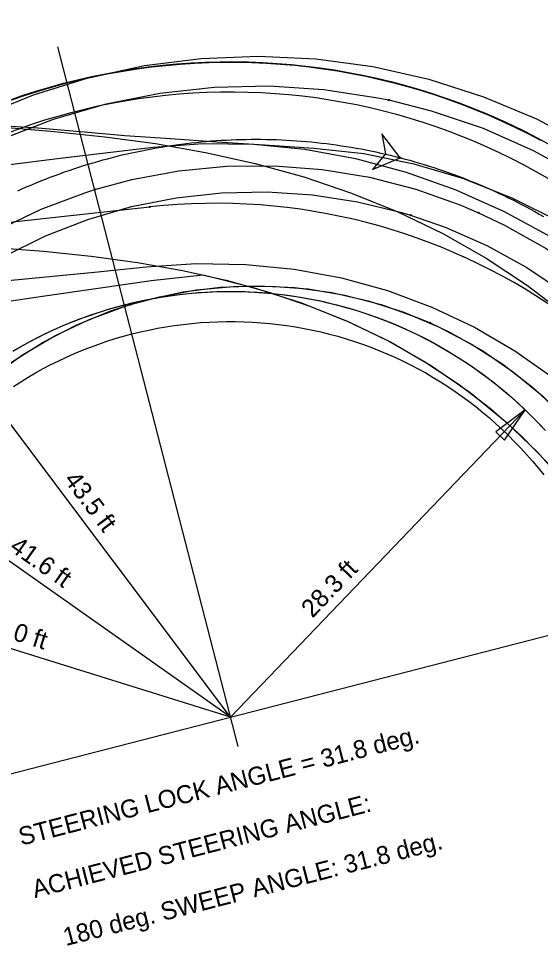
# Model space of a CAD drawing. Extents: x 916040 to 917457, y 328936 to 330267.
# Drawn here: x 916684.3 to 916719, y 329778.6 to 329840.2 of the extents above; entities that cross this region are included whole.
import ezdxf

# ---------------------------------------------------------------- set-up
doc = ezdxf.new("R2010")
doc.units = 0
for name, color, linetype in [('EB_LeftontoManchester_WB67', 7, 'Continuous'), ('EB_LeftontoManchester_WB67_v2', 7, 'Continuous'), ('SU_IntoDriveway', 7, 'Continuous'), ('SU_IntoDriveway_Lt', 7, 'Continuous'), ('SU_IntoDriveway_Rt', 7, 'Continuous')]:
    doc.layers.add(name, color=color, linetype=linetype)

msp = doc.modelspace()

# ---------------------------------------------------------------- linework, layer by layer
at = {"layer": 'EB_LeftontoManchester_WB67'}
msp.add_arc((916768.512, 329810.214), 100, 192.26429, 233.38938, dxfattribs=at)
at = {"layer": 'EB_LeftontoManchester_WB67_v2'}
msp.add_arc((916768.512, 329810.214), 100, 192.26429, 233.38938, dxfattribs=at)
at = {"layer": 'SU_IntoDriveway'}
for p, q in [((916698.918, 329791.868), (916686.933, 329838.355)), ((916698.419, 329793.805), (916672.246, 329828.591)), ((916698.419, 329793.805), (916664.439, 329817.747)), ((916698.419, 329793.805), (916718.006, 329814.228)), ((916655.805, 329782.818), (916741.033, 329804.791)), ((916698.419, 329793.805), (916662.129, 329805.103))]:
    msp.add_line(p, q, dxfattribs=at)
for points in [[(916683.678, 329834.802), (916684.581, 329835.115), (916685.49, 329835.408), (916686.405, 329835.682), (916687.326, 329835.935), (916688.252, 329836.168), (916689.184, 329836.381), (916690.119, 329836.573), (916691.059, 329836.745), (916692.002, 329836.896), (916692.949, 329837.026), (916693.898, 329837.136), (916694.849, 329837.224), (916695.802, 329837.292), (916696.756, 329837.339), (916697.711, 329837.365), (916698.666, 329837.37), (916699.621, 329837.354), (916700.576, 329837.317), (916701.529, 329837.26), (916702.481, 329837.181), (916703.431, 329837.081), (916704.379, 329836.961), (916705.324, 329836.82), (916706.265, 329836.658), (916707.203, 329836.476), (916708.136, 329836.273), (916709.065, 329836.05), (916709.989, 329835.806), (916710.907, 329835.543), (916711.819, 329835.259), (916712.725, 329834.955), (916713.624, 329834.631), (916714.515, 329834.288), (916715.399, 329833.925), (916716.274, 329833.544), (916717.141, 329833.142), (916717.999, 329832.723), (916718.848, 329832.284), (916719.687, 329831.827)], [(916683.89, 329834.843), (916684.793, 329835.151), (916685.703, 329835.44), (916686.619, 329835.709), (916687.54, 329835.958), (916688.467, 329836.186), (916689.399, 329836.394), (916690.335, 329836.581), (916691.274, 329836.748), (916692.218, 329836.895), (916693.164, 329837.02), (916694.113, 329837.125), (916695.064, 329837.209), (916696.016, 329837.272), (916696.97, 329837.315), (916697.924, 329837.336), (916698.878, 329837.336), (916699.833, 329837.316), (916700.786, 329837.274), (916701.739, 329837.212), (916702.69, 329837.129), (916703.639, 329837.025), (916704.585, 329836.9), (916705.528, 329836.754), (916706.468, 329836.588), (916707.405, 329836.401), (916708.336, 329836.194), (916709.263, 329835.966), (916710.185, 329835.718), (916711.101, 329835.45), (916712.011, 329835.162), (916712.915, 329834.854), (916713.811, 329834.527), (916714.701, 329834.179), (916715.582, 329833.813), (916716.455, 329833.427), (916717.319, 329833.022), (916718.175, 329832.598), (916719.02, 329832.155)], [(916683.501, 329832.602), (916684.355, 329832.919), (916685.216, 329833.218), (916686.083, 329833.498), (916686.957, 329833.759), (916687.835, 329834.001), (916688.719, 329834.223), (916689.608, 329834.426), (916690.5, 329834.61), (916691.397, 329834.773), (916692.297, 329834.918), (916693.2, 329835.042), (916694.105, 329835.146), (916695.013, 329835.231), (916695.922, 329835.296), (916696.832, 329835.34), (916697.743, 329835.365), (916698.655, 329835.37), (916699.566, 329835.355), (916700.477, 329835.32), (916701.386, 329835.265), (916702.295, 329835.19), (916703.201, 329835.095), (916704.105, 329834.98), (916705.007, 329834.845), (916705.905, 329834.691), (916706.8, 329834.517), (916707.69, 329834.323), (916708.576, 329834.11), (916709.458, 329833.878), (916710.334, 329833.626), (916711.204, 329833.356), (916712.068, 329833.066), (916712.925, 329832.757), (916713.776, 329832.43), (916714.619, 329832.084), (916715.455, 329831.719), (916716.282, 329831.336), (916717.1, 329830.936), (916717.91, 329830.517), (916718.71, 329830.081), (916719.501, 329829.627)], [(916683.501, 329832.602), (916684.355, 329832.919), (916685.216, 329833.218), (916686.083, 329833.498), (916686.957, 329833.759), (916687.835, 329834.001), (916688.719, 329834.223), (916689.608, 329834.426), (916690.5, 329834.61), (916691.397, 329834.773), (916692.297, 329834.918), (916693.2, 329835.042), (916694.105, 329835.146), (916695.013, 329835.231), (916695.922, 329835.296), (916696.832, 329835.34), (916697.743, 329835.365), (916698.655, 329835.37), (916699.566, 329835.355), (916700.477, 329835.32), (916701.386, 329835.265), (916702.295, 329835.19), (916703.201, 329835.095), (916704.105, 329834.98), (916705.007, 329834.845), (916705.905, 329834.691), (916706.8, 329834.517), (916707.69, 329834.323), (916708.576, 329834.11), (916709.458, 329833.878), (916710.334, 329833.626), (916711.204, 329833.356), (916712.068, 329833.066), (916712.925, 329832.757), (916713.776, 329832.43), (916714.619, 329832.084), (916715.455, 329831.719), (916716.282, 329831.336), (916717.1, 329830.936), (916717.91, 329830.517), (916718.71, 329830.081), (916719.501, 329829.627)], [(916683.943, 329818.123), (916684.48, 329818.434), (916685.023, 329818.734), (916685.574, 329819.022), (916686.13, 329819.297), (916686.692, 329819.561), (916687.26, 329819.812), (916687.833, 329820.05), (916688.411, 329820.276), (916688.994, 329820.489), (916689.581, 329820.689), (916690.173, 329820.876), (916690.769, 329821.051), (916691.368, 329821.212), (916691.971, 329821.36), (916692.577, 329821.495), (916693.186, 329821.616), (916693.797, 329821.724), (916694.41, 329821.819), (916695.026, 329821.9), (916695.643, 329821.967), (916696.261, 329822.021), (916696.88, 329822.062), (916697.5, 329822.089), (916698.121, 329822.102), (916698.741, 329822.102), (916699.362, 329822.088), (916699.982, 329822.06), (916700.601, 329822.019), (916701.219, 329821.964), (916701.836, 329821.896), (916702.451, 329821.814), (916703.065, 329821.719), (916703.676, 329821.611), (916704.284, 329821.489), (916704.89, 329821.353), (916705.492, 329821.205), (916706.091, 329821.043), (916706.687, 329820.868), (916707.278, 329820.68), (916707.865, 329820.48), (916708.448, 329820.266), (916709.026, 329820.04), (916709.599, 329819.801), (916710.166, 329819.549), (916710.728, 329819.286), (916711.283, 329819.01), (916711.833, 329818.721), (916712.376, 329818.421), (916712.912, 329818.109), (916713.442, 329817.786), (916713.964, 329817.45), (916714.479, 329817.104), (916714.986, 329816.746), (916715.485, 329816.377), (916715.976, 329815.998), (916716.458, 329815.607), (916716.932, 329815.207), (916717.397, 329814.795), (916717.852, 329814.374), (916718.299, 329813.943), (916718.736, 329813.503), (916719.164, 329813.054)], [(916683.943, 329818.123), (916684.48, 329818.434), (916685.023, 329818.734), (916685.574, 329819.022), (916686.13, 329819.297), (916686.692, 329819.561), (916687.26, 329819.812), (916687.833, 329820.05), (916688.411, 329820.276), (916688.994, 329820.489), (916689.581, 329820.689), (916690.173, 329820.876), (916690.769, 329821.051), (916691.368, 329821.212), (916691.971, 329821.36), (916692.577, 329821.495), (916693.186, 329821.616), (916693.797, 329821.724), (916694.41, 329821.819), (916695.026, 329821.9), (916695.643, 329821.967), (916696.261, 329822.021), (916696.88, 329822.062), (916697.5, 329822.089), (916698.121, 329822.102), (916698.741, 329822.102), (916699.362, 329822.088), (916699.982, 329822.06), (916700.601, 329822.019), (916701.219, 329821.964), (916701.836, 329821.896), (916702.451, 329821.814), (916703.065, 329821.719), (916703.676, 329821.611), (916704.284, 329821.489), (916704.89, 329821.353), (916705.492, 329821.205), (916706.091, 329821.043), (916706.687, 329820.868), (916707.278, 329820.68), (916707.865, 329820.48), (916708.448, 329820.266), (916709.026, 329820.04), (916709.599, 329819.801), (916710.166, 329819.549), (916710.728, 329819.286), (916711.283, 329819.01), (916711.833, 329818.721), (916712.376, 329818.421), (916712.912, 329818.109), (916713.442, 329817.786), (916713.964, 329817.45), (916714.479, 329817.104), (916714.986, 329816.746), (916715.485, 329816.377), (916715.976, 329815.998), (916716.458, 329815.607), (916716.932, 329815.207), (916717.397, 329814.795), (916717.852, 329814.374), (916718.299, 329813.943), (916718.736, 329813.503), (916719.164, 329813.054)], [(916684.13, 329818.233), (916684.669, 329818.54), (916685.215, 329818.836), (916685.767, 329819.119), (916686.325, 329819.391), (916686.889, 329819.65), (916687.458, 329819.896), (916688.033, 329820.13), (916688.613, 329820.351), (916689.197, 329820.56), (916689.786, 329820.756), (916690.379, 329820.938), (916690.976, 329821.108), (916691.577, 329821.265), (916692.18, 329821.408), (916692.787, 329821.538), (916693.397, 329821.655), (916694.008, 329821.758), (916694.622, 329821.848), (916695.238, 329821.924), (916695.856, 329821.987), (916696.474, 329822.037), (916697.094, 329822.073), (916697.714, 329822.095), (916698.334, 329822.103), (916698.955, 329822.098), (916699.575, 329822.08), (916700.195, 329822.048), (916700.813, 329822.002), (916701.431, 329821.943), (916702.047, 329821.87), (916702.662, 329821.783), (916703.274, 329821.684), (916703.884, 329821.57), (916704.492, 329821.444), (916705.096, 329821.304), (916705.698, 329821.151), (916706.296, 329820.985), (916706.89, 329820.805), (916707.48, 329820.613), (916708.065, 329820.408), (916708.646, 329820.19), (916709.222, 329819.96), (916709.793, 329819.716), (916710.359, 329819.461), (916710.918, 329819.193), (916711.472, 329818.913), (916712.019, 329818.62), (916712.56, 329818.316), (916713.094, 329818), (916713.621, 329817.673), (916714.141, 329817.333), (916714.653, 329816.983), (916715.157, 329816.622), (916715.653, 329816.249), (916716.141, 329815.866), (916716.621, 329815.472), (916717.091, 329815.068), (916717.553, 329814.653), (916718.006, 329814.228), (916718.453, 329813.79), (916718.9, 329813.333), (916719.345, 329812.859)], [(916683.987, 329815.792), (916684.473, 329816.103), (916684.966, 329816.404), (916685.465, 329816.693), (916685.97, 329816.972), (916686.481, 329817.239), (916686.998, 329817.496), (916687.52, 329817.74), (916688.048, 329817.973), (916688.581, 329818.195), (916689.118, 329818.405), (916689.66, 329818.603), (916690.206, 329818.789), (916690.756, 329818.963), (916691.309, 329819.125), (916691.867, 329819.275), (916692.427, 329819.412), (916692.99, 329819.537), (916693.555, 329819.65), (916694.123, 329819.751), (916694.693, 329819.839), (916695.265, 329819.914), (916695.839, 329819.977), (916696.413, 329820.027), (916696.989, 329820.065), (916697.565, 329820.09), (916698.142, 329820.102), (916698.718, 329820.102), (916699.295, 329820.089), (916699.871, 329820.063), (916700.447, 329820.025), (916701.021, 329819.974), (916701.594, 329819.911), (916702.166, 329819.835), (916702.736, 329819.746), (916703.304, 329819.645), (916703.869, 329819.532), (916704.432, 329819.406), (916704.992, 329819.268), (916705.549, 329819.118), (916706.102, 329818.955), (916706.652, 329818.781), (916707.198, 329818.594), (916707.739, 329818.396), (916708.276, 329818.186), (916708.808, 329817.963), (916709.336, 329817.73), (916709.858, 329817.485), (916710.374, 329817.228), (916710.885, 329816.96), (916711.39, 329816.681), (916711.888, 329816.391), (916712.38, 329816.091), (916712.865, 329815.779), (916713.344, 329815.457), (916713.815, 329815.125), (916714.279, 329814.782), (916714.735, 329814.429), (916715.183, 329814.066), (916715.623, 329813.694), (916716.055, 329813.312), (916716.479, 329812.92), (916716.894, 329812.519), (916717.303, 329812.108), (916717.704, 329811.687), (916718.099, 329811.257), (916718.487, 329810.819), (916718.868, 329810.373), (916719.243, 329809.92)]]:
    msp.add_lwpolyline(points, dxfattribs=at)
msp.add_lwpolyline([(916718.006, 329814.228), (916716.056, 329812.773), (916716.633, 329812.219)], close=True, dxfattribs=at)
at = {"layer": 'SU_IntoDriveway_Lt'}
msp.add_line((916680.471, 329826.341), (916693.053, 329827.719), dxfattribs=at)
for points in [[(916652.031, 329840.237), (916654.673, 329838.808), (916657.374, 329837.564), (916660.126, 329836.507), (916662.92, 329835.639), (916665.742, 329834.949), (916668.579, 329834.409), (916671.423, 329833.993), (916674.267, 329833.681), (916677.108, 329833.457), (916679.946, 329833.304), (916682.778, 329833.16), (916685.602, 329832.974), (916688.453, 329832.732), (916691.394, 329832.467), (916694.42, 329832.262), (916697.507, 329832.052), (916700.681, 329831.836), (916703.955, 329831.614), (916707.281, 329831.263), (916710.611, 329830.59), (916713.914, 329829.603), (916717.16, 329828.311), (916720.317, 329826.726)], [(916654.001, 329839.15), (916656.558, 329837.917), (916659.178, 329836.848), (916661.854, 329835.947), (916664.614, 329835.205), (916667.505, 329834.598), (916670.498, 329834.116), (916673.568, 329833.749), (916676.737, 329833.473), (916680.01, 329833.24), (916683.344, 329833.008), (916686.707, 329832.735), (916690.076, 329832.385), (916693.434, 329831.93), (916696.766, 329831.345), (916700.056, 329830.61), (916703.293, 329829.712), (916706.462, 329828.639), (916709.549, 329827.385), (916712.538, 329825.945), (916715.415, 329824.317), (916718.165, 329822.503), (916720.773, 329820.507)], [(916653.657, 329835.106), (916656.452, 329833.749), (916659.329, 329832.586), (916662.275, 329831.621), (916665.275, 329830.858), (916668.317, 329830.299), (916671.388, 329829.946), (916674.474, 329829.8), (916677.561, 329829.861), (916680.635, 329830.128), (916683.755, 329830.536), (916686.91, 329830.934), (916690.086, 329831.319), (916693.281, 329831.697), (916696.59, 329831.934), (916699.955, 329831.884), (916703.347, 329831.548), (916706.735, 329830.931), (916710.092, 329830.035), (916713.39, 329828.864), (916716.602, 329827.425), (916719.704, 329825.724)], [(916653.282, 329830.618), (916656.363, 329829.359), (916659.514, 329828.296), (916662.739, 329827.428), (916666.036, 329826.734), (916669.379, 329826.195), (916672.748, 329825.791), (916676.12, 329825.496), (916679.467, 329825.259), (916682.763, 329825.029), (916685.992, 329824.767), (916689.149, 329824.439), (916692.228, 329824.021), (916695.226, 329823.494), (916698.14, 329822.843), (916700.966, 329822.058), (916703.698, 329821.132), (916706.33, 329820.061), (916708.855, 329818.843), (916711.265, 329817.478), (916713.552, 329815.968), (916715.706, 329814.316), (916717.719, 329812.529), (916719.58, 329810.613)], [(916651.315, 329827.717), (916654.553, 329826.27), (916657.882, 329825.037), (916661.289, 329824.025), (916664.758, 329823.238), (916668.274, 329822.681), (916671.821, 329822.357), (916675.383, 329822.267), (916678.945, 329822.413), (916682.455, 329822.723), (916685.93, 329823.051), (916689.382, 329823.392), (916692.813, 329823.74), (916696.146, 329823.953), (916699.43, 329823.901), (916702.653, 329823.581), (916705.8, 329822.998), (916708.854, 329822.155), (916711.801, 329821.062), (916714.624, 329819.726), (916717.307, 329818.16), (916719.833, 329816.377)], [(916653.951, 329825.07), (916657.325, 329823.778), (916660.787, 329822.71), (916664.319, 329821.874), (916667.906, 329821.273), (916671.531, 329820.911), (916675.177, 329820.791), (916678.827, 329820.913), (916682.465, 329821.278), (916686.072, 329821.805), (916689.629, 329822.327), (916693.143, 329822.836), (916696.599, 329823.206), (916699.867, 329822.383), (916703.061, 329821.364), (916706.13, 329820.149), (916709.045, 329818.743), (916711.787, 329817.152), (916714.342, 329815.389), (916716.699, 329813.467), (916718.849, 329811.4), (916720.787, 329809.203)]]:
    msp.add_lwpolyline(points, dxfattribs=at)
msp.add_circle((916693.053, 329827.719), 0.0417, dxfattribs=at)
msp.add_circle((916693.053, 329827.719), 0.0417, dxfattribs=at)
msp.add_arc((916697.41, 329787.957), 40, 14.33728, 96.25336, dxfattribs=at)
at = {"layer": 'SU_IntoDriveway_Rt'}
for points in [[(916676.441, 329830.799), (916678.399, 329831.985), (916681.79, 329833.73), (916685.321, 329835.173), (916688.964, 329836.303), (916692.691, 329837.111), (916696.475, 329837.592), (916700.286, 329837.741), (916704.096, 329837.558), (916707.875, 329837.043), (916711.595, 329836.201), (916715.228, 329835.039), (916718.745, 329833.564), (916722.121, 329831.789), (916725.329, 329829.726), (916728.346, 329827.392), (916731.147, 329824.804), (916733.713, 329821.982), (916736.023, 329818.947), (916738.06, 329815.722), (916738.615, 329814.721)], [(916660.125, 329801.822), (916660.008, 329805.599), (916661.156, 329809.15), (916662.624, 329812.483), (916664.377, 329815.676), (916666.401, 329818.705), (916668.682, 329821.545), (916671.201, 329824.176), (916673.94, 329826.578), (916676.877, 329828.732), (916679.991, 329830.621), (916683.258, 329832.233), (916686.652, 329833.554), (916690.149, 329834.574), (916693.721, 329835.285), (916697.342, 329835.683), (916700.984, 329835.764), (916704.619, 329835.527), (916708.219, 329834.975), (916708.933, 329834.827)], [(916708.933, 329834.827), (916711.758, 329834.111), (916715.208, 329832.943), (916718.543, 329831.478), (916721.737, 329829.728), (916724.768, 329827.707), (916727.61, 329825.429), (916730.244, 329822.912), (916732.648, 329820.176), (916733.541, 329819.025)], [(916684.288, 329828.796), (916684.592, 329828.932), (916684.898, 329829.066), (916685.204, 329829.197), (916685.512, 329829.326), (916685.82, 329829.451), (916686.13, 329829.574), (916686.441, 329829.695), (916686.753, 329829.813), (916687.066, 329829.927), (916687.38, 329830.04), (916687.694, 329830.149), (916688.01, 329830.256), (916688.327, 329830.36), (916688.644, 329830.461), (916688.963, 329830.559), (916689.282, 329830.655), (916689.602, 329830.748), (916689.923, 329830.838), (916690.245, 329830.925), (916690.567, 329831.01), (916690.891, 329831.091), (916691.215, 329831.17), (916691.539, 329831.246), (916691.864, 329831.319), (916692.19, 329831.39), (916692.517, 329831.457), (916692.844, 329831.522), (916693.171, 329831.584), (916693.499, 329831.642), (916693.828, 329831.699), (916694.157, 329831.752), (916694.486, 329831.802), (916694.816, 329831.849), (916695.147, 329831.894), (916695.477, 329831.936), (916695.808, 329831.974), (916696.14, 329832.01), (916696.472, 329832.043), (916696.803, 329832.073), (916697.136, 329832.101), (916697.468, 329832.125), (916697.801, 329832.146), (916698.134, 329832.165), (916698.467, 329832.181), (916698.8, 329832.193), (916699.133, 329832.203), (916699.466, 329832.21), (916699.799, 329832.214), (916700.133, 329832.215), (916700.466, 329832.213), (916700.799, 329832.208), (916701.133, 329832.201), (916701.466, 329832.19), (916701.799, 329832.177), (916702.132, 329832.16), (916702.465, 329832.141), (916702.797, 329832.119), (916703.13, 329832.094), (916703.462, 329832.066), (916703.794, 329832.035), (916704.125, 329832.001), (916704.457, 329831.965), (916704.787, 329831.925), (916705.118, 329831.883), (916705.448, 329831.837), (916705.778, 329831.789), (916706.108, 329831.738), (916706.437, 329831.684), (916706.765, 329831.628), (916707.093, 329831.568), (916707.42, 329831.505), (916707.747, 329831.44), (916708.074, 329831.372), (916708.399, 329831.301), (916708.724, 329831.227), (916709.049, 329831.15), (916709.372, 329831.071), (916709.695, 329830.988)], [(916689.409, 329828.879), (916691.867, 329829.539), (916694.994, 329830.12), (916698.16, 329830.426), (916701.34, 329830.456), (916704.512, 329830.208), (916707.649, 329829.686), (916710.729, 329828.892), (916713.728, 329827.832), (916714.9, 329827.336)], [(916709.695, 329830.988), (916710.018, 329830.903), (916710.339, 329830.815), (916710.66, 329830.724), (916710.98, 329830.631), (916711.299, 329830.534), (916711.617, 329830.435), (916711.934, 329830.333), (916712.251, 329830.229), (916712.566, 329830.121), (916712.881, 329830.011), (916713.195, 329829.898), (916713.507, 329829.782), (916713.819, 329829.664), (916714.129, 329829.543), (916714.439, 329829.419), (916714.747, 329829.293), (916715.055, 329829.164), (916715.361, 329829.032), (916715.666, 329828.897), (916715.97, 329828.76), (916716.272, 329828.62), (916716.574, 329828.478), (916716.874, 329828.333), (916717.172, 329828.185), (916717.47, 329828.035), (916717.766, 329827.882), (916718.061, 329827.726), (916718.355, 329827.568), (916718.647, 329827.408), (916718.937, 329827.245), (916719.227, 329827.079)], [(916665.377, 329782.524), (916664.541, 329785.79), (916663.959, 329788.933), (916663.656, 329792.099), (916663.629, 329795.28), (916663.88, 329798.451), (916664.406, 329801.588), (916665.203, 329804.667), (916666.265, 329807.666), (916667.584, 329810.56), (916669.151, 329813.328), (916670.952, 329815.95), (916672.975, 329818.404), (916675.205, 329820.673), (916677.623, 329822.739), (916680.212, 329824.587), (916682.952, 329826.202), (916685.823, 329827.572), (916688.802, 329828.687), (916689.409, 329828.879)], [(916667.844, 329803.923), (916667.812, 329806.71), (916668.948, 329809.381), (916670.407, 329812.035), (916672.091, 329814.552), (916673.988, 329816.913), (916676.084, 329819.099), (916678.362, 329821.095), (916680.805, 329822.884), (916683.394, 329824.454), (916686.111, 329825.793), (916688.934, 329826.889), (916691.841, 329827.736), (916694.812, 329828.326), (916697.822, 329828.655), (916700.85, 329828.721), (916703.872, 329828.523), (916706.865, 329828.062), (916709.807, 329827.343), (916710.387, 329827.168)], [(916714.9, 329827.336), (916716.624, 329826.516), (916719.394, 329824.952), (916722.017, 329823.153), (916724.473, 329821.132), (916726.744, 329818.905), (916728.813, 329816.489), (916730.676, 329813.886), (916732.407, 329811.043), (916734.015, 329808.062), (916735.521, 329805.02), (916736.959, 329801.953), (916738.338, 329798.858), (916739.658, 329795.744), (916740.929, 329792.618), (916742.163, 329789.488), (916743.371, 329786.359), (916744.562, 329783.229), (916745.741, 329780.1), (916746.912, 329776.97), (916747.262, 329776.031)], [(916710.387, 329827.168), (916712.674, 329826.37), (916715.447, 329825.15), (916718.102, 329823.694), (916720.62, 329822.013), (916722.983, 329820.118), (916725.171, 329818.025), (916727.169, 329815.749), (916728.961, 329813.307), (916729.617, 329812.289)], [(916691.41, 329821.122), (916692.84, 329821.539), (916695.267, 329822.066), (916697.731, 329822.379), (916700.212, 329822.477), (916702.692, 329822.358), (916705.153, 329822.023), (916707.575, 329821.476), (916709.941, 329820.719), (916712.231, 329819.76), (916714.429, 329818.604), (916716.518, 329817.262), (916718.482, 329815.743), (916720.307, 329814.058), (916721.978, 329812.221), (916723.482, 329810.245), (916724.827, 329808.157), (916726.058, 329805.999), (916727.209, 329803.796), (916728.305, 329801.564), (916728.627, 329800.891)], [(916691.78, 329821.239), (916693.7, 329821.752), (916696.142, 329822.203), (916698.614, 329822.439), (916701.097, 329822.46), (916703.573, 329822.264), (916706.022, 329821.853), (916708.426, 329821.23), (916710.767, 329820.401), (916711.681, 329820.012)], [(916673.096, 329784.625), (916672.333, 329787.599), (916671.878, 329790.074), (916671.643, 329792.546), (916671.625, 329795.029), (916671.824, 329797.505), (916672.237, 329799.953), (916672.862, 329802.357), (916673.694, 329804.697), (916674.726, 329806.955), (916675.951, 329809.115), (916677.36, 329811.16), (916678.942, 329813.075), (916680.684, 329814.844), (916682.574, 329816.455), (916684.597, 329817.895), (916686.738, 329819.154), (916688.98, 329820.221), (916691.307, 329821.089), (916691.78, 329821.239)], [(916675.516, 329808.395), (916676.819, 329810.418), (916678.359, 329812.408), (916680.046, 329814.231), (916681.885, 329815.9), (916683.862, 329817.402), (916685.962, 329818.727), (916688.17, 329819.863), (916690.469, 329820.803), (916691.41, 329821.122)], [(916711.681, 329820.012), (916713.026, 329819.37), (916715.187, 329818.147), (916717.234, 329816.74), (916719.15, 329815.161), (916720.921, 329813.42), (916722.534, 329811.532), (916724, 329809.477), (916725.465, 329807.067), (916726.905, 329804.395), (916728.313, 329801.548), (916729.688, 329798.618), (916731.002, 329795.668), (916732.27, 329792.675), (916733.502, 329789.644), (916734.71, 329786.581), (916735.901, 329783.495), (916737.081, 329780.396), (916738.252, 329777.288), (916739.416, 329774.174), (916739.765, 329773.239)]]:
    msp.add_lwpolyline(points, dxfattribs=at)
msp.add_lwpolyline([(916709.695, 329830.988), (916708.466, 329832.566), (916708.727, 329831.24), (916707.854, 329830.209)], close=True, dxfattribs=at)
for centre in [(916708.933, 329834.827), (916708.933, 329834.827), (916709.695, 329830.988), (916709.695, 329830.988), (916689.409, 329828.879), (916689.409, 329828.879), (916714.9, 329827.336), (916714.9, 329827.336), (916710.387, 329827.168), (916710.387, 329827.168), (916691.41, 329821.122), (916691.41, 329821.122), (916691.78, 329821.239), (916691.78, 329821.239), (916711.681, 329820.012), (916711.681, 329820.012)]:
    msp.add_circle(centre, 0.0417, dxfattribs=at)

# ---------------------------------------------------------------- texts
at = {"layer": 'SU_IntoDriveway'}
for s, rotation, p in [('43.5 ft', 306.95691, (916687.302, 329809.579)), ('41.6 ft', 324.83191, (916683.665, 329804.934)), ('28.3 ft', 46.19814, (916703.862, 329800.347)), ('38.0 ft', 342.70691, (916681.763, 329799.618)), ('STEERING LOCK ANGLE = 31.8 deg.', 14.45691, (916684.511, 329785.262)), ('ACHIEVED STEERING ANGLE:', 14.45691, (916685.41, 329781.776)), ('180 deg. SWEEP ANGLE: 31.8 deg.', 14.45691, (916687.47, 329778.59))]:
    msp.add_text(s, height=1.2, rotation=rotation, dxfattribs=at).set_placement(p)

doc.saveas('drawing.dxf')
